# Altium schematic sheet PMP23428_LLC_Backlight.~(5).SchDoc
size 431 x 279 mm; Date: Not shown in title block; ApprovedBy: Not shown in title block; CheckedBy: Not shown in title block; Author: Not shown in title block; CompanyName: Not shown in title block; Engineer: Not shown in title block; Organization: Not shown in title block; Address1: Not shown in title block; Address2: Not shown in title block; Address3: Not shown in title block; Address4: Not shown in title block; DocumentNumber: 2; Revision: Use project parameter SCH_Rev; SheetNumber: 2; SheetTotal: 4; PageSetup: Record=PageOptions¦CenterHorizontal=True¦CenterVertical=True¦PrintScale=1.00¦XCorrection=1.00¦YCorrection=1.00¦PrintKind=0¦BorderSize=5000000¦LeftOffset=0¦BottomOffset=0¦Orientation=2¦PaperLength=1000¦PaperWidth=1000¦Scale=100¦PaperSource=15¦PrintQuality=600¦MediaType=1¦DitherType=10¦PaperKind=Letter¦PrintScaleMode=1
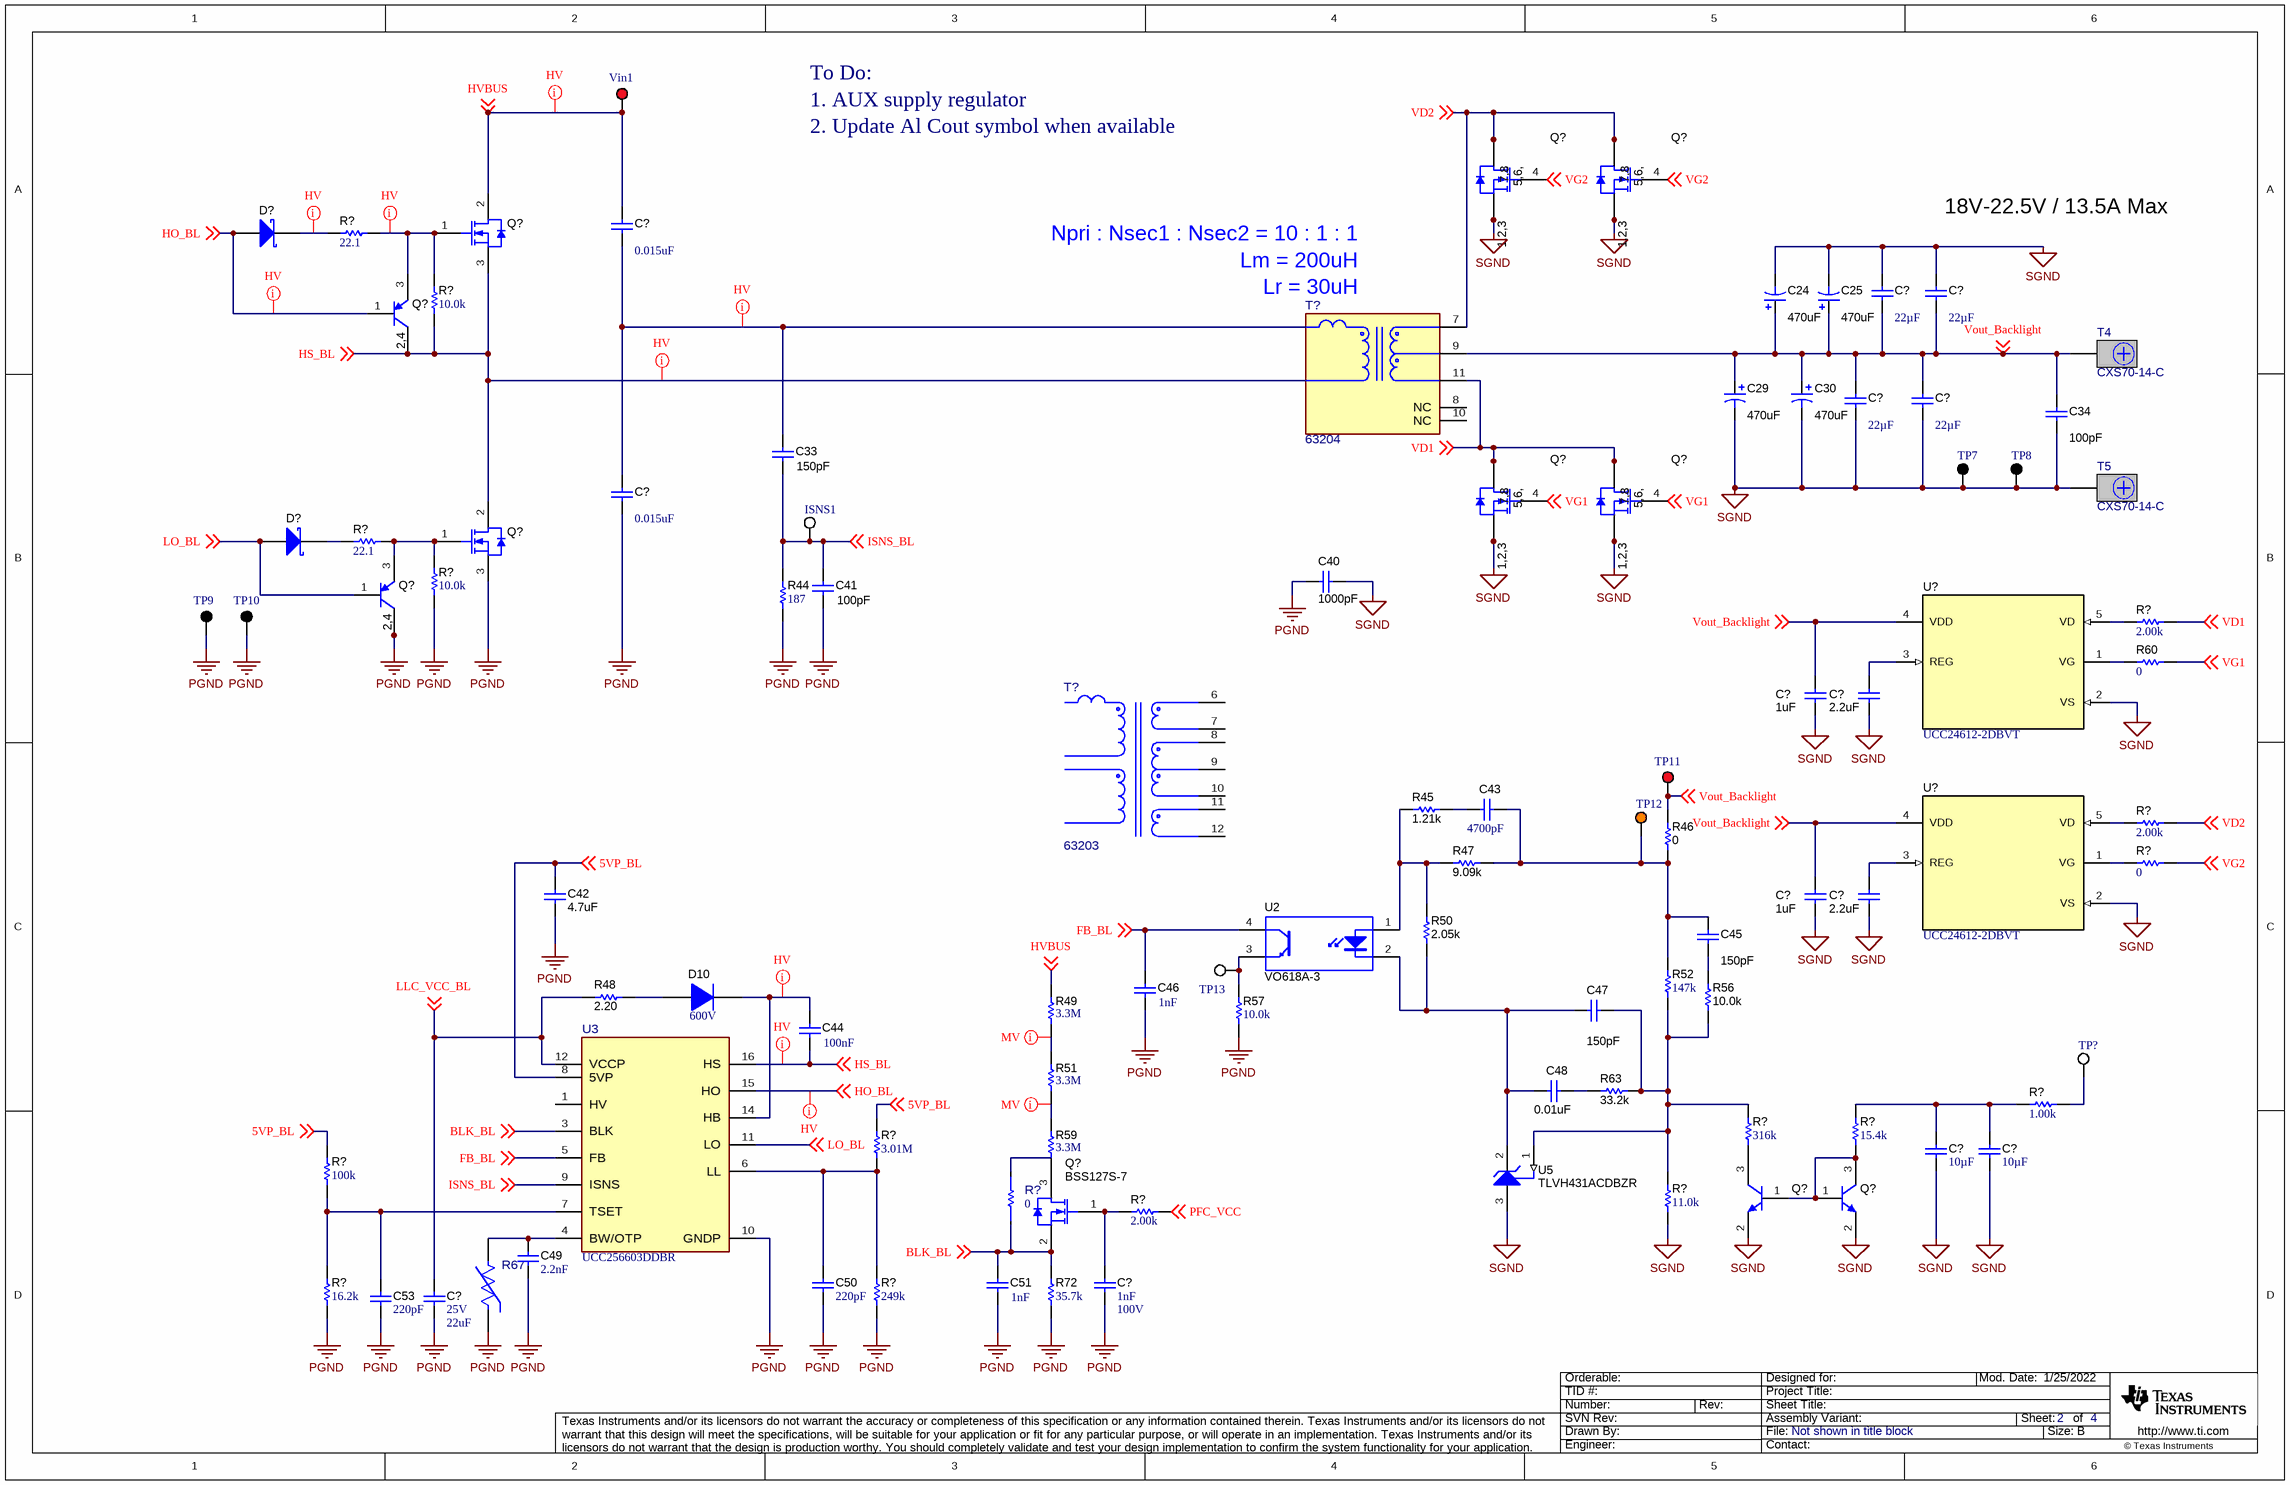
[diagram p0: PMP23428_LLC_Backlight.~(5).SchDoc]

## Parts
(Parts that share a designator on the sheet are numbered #1, #2 ... from top to bottom, then left to right.)
C24  ValueDisplayed: 470uF  [HW_1000x1600]  (hidden comment: UHW1V471MPD)
C25  ValueDisplayed: 470uF  [HW_1000x1600]  (hidden comment: UHW1V471MPD)
C29  ValueDisplayed: 470uF  [HW_1000x1600]  (hidden comment: UHW1V471MPD)
C30  ValueDisplayed: 470uF  [HW_1000x1600]  (hidden comment: UHW1V471MPD)
C33  ValueDisplayed: 150pF  [1206L]  (hidden comment: GRM31A5C2J151JW01D)
C34  ValueDisplayed: 100pF  [0603L]  (hidden comment: 06035A101FAT2A)
C40  ValueDisplayed: 1000pF  [CD45_700x600x1100]  (hidden comment: CD45-E2GA102M-NKA)
C41  ValueDisplayed: 100pF  [1206L]  (hidden comment: 12061A101JAT2A)
C42  ValueDisplayed: 4.7uF  [1206L]  (hidden comment: C3216X7R1E475K085AB)
C43  ValueDisplayed: 4700pF  [0603L]  (hidden comment: C0603C472J1GAC7867)
C44  Cap_F: 100nF  [1206_180L]  (hidden comment: GRM31C5C1E104JA01L)
C45  ValueDisplayed: 150pF  [0402L]  (hidden comment: 885012005062)
C46  Cap_F: 1nF  [1206L]  (hidden comment: 12061A102JAT2A)
C47  ValueDisplayed: 150pF  [0402L]  (hidden comment: 885012005062)
C48  ValueDisplayed: 0.01uF  [0603L]  (hidden comment: 06031C103JAT2A)
C49  Cap_F: 2.2nF  [0603]  (hidden comment: C0603X222K5RACTU)
C50  Cap_F: 220pF  [0603]  (hidden comment: C0603X221K5RACTU)
C51  Cap_F: 1nF  [0402L]  (hidden comment: 04025C102JAT2A)
C53  Cap_F: 220pF  [0603]  (hidden comment: C0603X221K5RACTU)
C?#1  ValueDisplayed: 0.015uF  [PHE426_1300x400x900]  (hidden comment: PHE426MA5150JR05)
C?#2  ValueDisplayed: 22µF  [1210]  (hidden comment: GMK325BJ226MM-P)
C?#3  ValueDisplayed: 22µF  [1210]  (hidden comment: GMK325BJ226MM-P)
C?#4  ValueDisplayed: 22µF  [1210]  (hidden comment: GMK325BJ226MM-P)
C?#5  ValueDisplayed: 22µF  [1210]  (hidden comment: GMK325BJ226MM-P)
C?#6  ValueDisplayed: 0.015uF  [PHE426_1300x400x900]  (hidden comment: PHE426MA5150JR05)
C?#7  ValueDisplayed: 1uF  [0603L]  (hidden comment: GRM188R71C105KE15D)
C?#8  ValueDisplayed: 2.2uF  [0805L]  (hidden comment: C2012X7R1V225K085AC)
C?#9  ValueDisplayed: 1uF  [0603L]  (hidden comment: GRM188R71C105KE15D)
C?#10  ValueDisplayed: 2.2uF  [0805L]  (hidden comment: C2012X7R1V225K085AC)
C?#11  ValueDisplayed: 10µF  [1206_180]  (hidden comment: C1206C106J3RACAUTO)
C?#12  ValueDisplayed: 10µF  [1206_180]  (hidden comment: C1206C106J3RACAUTO)
C?#13  Cap_F: 1nF  VDC_V: 100V  [0603]  (hidden comment: C1608X7R2A102K080AA)
C?#14  VDC_V: 25V  ValueDisplayed: 22uF  [1206_190]  (hidden comment: TMK316BBJ226ML-T)
D10  Vr_V: 600V  [SMAF]  (hidden comment: ES1JAF)
D?#1  PMEG3010EGWJ  [SOD-123]  (value not drawn)
D?#2  PMEG3010EGWJ  [SOD-123]  (value not drawn)
ISNS1  5012  [Keystone5012]  (value not drawn)
Q?#1  CSD19532Q5B  [DNK0008A]  (value not drawn)
Q?#2  CSD19532Q5B  [DNK0008A]  (value not drawn)
Q?#3  IPP60R099C7XKSA1  [TO-220AB]  (value not drawn)
Q?#4  FZT593TA  [SOT-223]  (value not drawn)
Q?#5  CSD19532Q5B  [DNK0008A]  (value not drawn)
Q?#6  CSD19532Q5B  [DNK0008A]  (value not drawn)
Q?#7  IPP60R099C7XKSA1  [TO-220AB]  (value not drawn)
Q?#8  FZT593TA  [SOT-223]  (value not drawn)
Q?#9  MMBTA05LT1G  [SOT-23]  (value not drawn)
Q?#10  MMBTA05LT1G  [SOT-23]  (value not drawn)
Q?#11  BSS127S-7  [SOT-23]
R44  ValueDisplayed: 187  [1206]  (hidden comment: RC1206FR-07187RL)
R45  ValueDisplayed: 1.21k  [0603L]  (hidden comment: RC0603FR-071K21L)
R46  ValueDisplayed: 0  [0402L]  (hidden comment: RC0402JR-070RL)
R47  ValueDisplayed: 9.09k  [0603L]  (hidden comment: RC0603FR-079K09L)
R48  ValueDisplayed: 2.20  [0603L]  (hidden comment: ERJ-3RQF2R2V)
R49  Res_ohm: 3.3M  [FP-KTR18EZPF3304_1206-MFG]  (hidden comment: KTR18EZPF3304)
R50  ValueDisplayed: 2.05k  [0603L]  (hidden comment: RC0603FR-072K05L)
R51  Res_ohm: 3.3M  [FP-KTR18EZPF3304_1206-MFG]  (hidden comment: KTR18EZPF3304)
R52  ValueDisplayed: 147k  [0603L]  (hidden comment: RC0603FR-07147KL)
R56  ValueDisplayed: 10.0k  [0603L]  (hidden comment: ERJ-3EKF1002V)
R57  ValueDisplayed: 10.0k  [0402L]  (hidden comment: ERJ-2RKF1002X)
R59  Res_ohm: 3.3M  [FP-KTR18EZPF3304_1206-MFG]  (hidden comment: KTR18EZPF3304)
R60  ValueDisplayed: 0  [0603L]  (hidden comment: RC0603JR-070RL)
R63  ValueDisplayed: 33.2k  [0603L]  (hidden comment: RC0603FR-0733K2L)
R67  B57371V2474J060  [FP-B57371V2474J060_0603-MFG]  (value not drawn)
R72  ValueDisplayed: 35.7k  [0603]  (hidden comment: RT0603BRD0735K7L)
R?#1  ValueDisplayed: 22.1  [0603]  (hidden comment: RC0603FR-0722R1L)
R?#2  ValueDisplayed: 10.0k  [0603]  (hidden comment: M55342K12B10E0T)
R?#3  ValueDisplayed: 22.1  [0603]  (hidden comment: RC0603FR-0722R1L)
R?#4  ValueDisplayed: 10.0k  [0603]  (hidden comment: M55342K12B10E0T)
R?#5  ValueDisplayed: 2.00k  [0603]  (hidden comment: RC0603FR-072KL)
R?#6  ValueDisplayed: 2.00k  [0603]  (hidden comment: RC0603FR-072KL)
R?#7  ValueDisplayed: 0  [0603L]  (hidden comment: RC0603JR-070RL)
R?#8  ValueDisplayed: 1.00k  [0603L]  (hidden comment: CRCW06031K00FKEA)
R?#9  ValueDisplayed: 316k  [0603L]  (hidden comment: CRCW0603316KFKEA)
R?#10  ValueDisplayed: 15.4k  [0603L]  (hidden comment: RC0603FR-0715K4L)
R?#11  ValueDisplayed: 3.01M  [0603]  (hidden comment: RC0603FR-073M01L)
R?#12  ValueDisplayed: 100k  [0603]  (hidden comment: RC0603FR-07100KL)
R?#13  ValueDisplayed: 11.0k  [0603]  (hidden comment: RC0603FR-0711KL)
R?#14  ValueDisplayed: 2.00k  [0603]  (hidden comment: RC0603FR-072KL)
R?#15  value 0  [FP-RMCF1206ZT0R00_1206-MFG]  (hidden comment: RMCF1206ZT0R00)
R?#16  ValueDisplayed: 16.2k  [0603]  (hidden comment: RC0603FR-0716K2L)
R?#17  ValueDisplayed: 249k  [0603]  (hidden comment: RC0603FR-07249KL)
T4  CXS70-14-C  [Panduit_CXS70-14-C]
T5  CXS70-14-C  [Panduit_CXS70-14-C]
T?#1  63204  [FP-63204_PTH_XRMS_80MM0_64MM0-MFG]
T?#2  63203  [FP-63203_W80MM0_H64MM0-MFG]
TP7  5011  [Keystone5011]  (value not drawn)
TP8  5011  [Keystone5011]  (value not drawn)
TP9  5011  [Keystone5011]  (value not drawn)
TP10  5011  [Keystone5011]  (value not drawn)
TP11  5010  [Keystone5010]  (value not drawn)
TP12  5013  [Keystone5013]  (value not drawn)
TP13  5012  [Keystone5012]  (value not drawn)
TP?  5012  [Keystone5012]  (value not drawn)
U2  VO618A-3  [DIP-4]
U3  UCC256603DDBR  [DDB0014A-MFG]
U5  TLVH431ACDBZR  [DBZ0003A_N]
U?#1  UCC24612-2DBVT  [DBV0005A_N]
U?#2  UCC24612-2DBVT  [DBV0005A_N]
Vin1  5010  [Keystone5010]  (value not drawn)

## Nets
PGND: C40.2 C41.2 C42.2 C46.2 C49.2 C50.2 C51.2 C53.2 C?#6.2 C?#13.2 C?#14.2 Q?#7.3(S) Q?#8.2(C) Q?#8.4(C) R44.1 R57.1 R67.1 R72.1 R?#4.1 R?#16.1 R?#17.1 TP9.1 TP10.1 U3.10(GNDP)
SGND: C24.2(-) C25.2(-) C29.2(-) C30.2(-) C34.2 C40.1 C?#2.1 C?#3.1 C?#4.2 C?#5.2 C?#7.2 C?#8.2 C?#9.2 C?#10.2 C?#11.2 C?#12.2 Q?#1.1(S) Q?#1.2(S) Q?#1.3(S) Q?#2.1(S) Q?#2.2(S) Q?#2.3(S) Q?#5.1(S) Q?#5.2(S) Q?#5.3(S) Q?#6.1(S) Q?#6.2(S) Q?#6.3(S) Q?#9.2(E) Q?#10.2(E) R?#13.1 T5.1 TP7.1 TP8.1 U5.3(ANODE) U?#1.2(VS) U?#2.2(VS)
5VP_BL: C42.1 R?#11.2 R?#12.2 U3.8(5VP) ; off-sheet 5VP_BL
BLK_BL: C51.1 Q?#11.2(S) R72.2 R?#15.1 U3.3(BLK) ; off-sheet BLK_BL
FB_BL: C46.1 U2.4(C) U3.5(FB) ; off-sheet FB_BL
HO_BL: D?#1.2(A) Q?#4.1(B) U3.15(HO) ; off-sheet HO_BL
HS_BL: C44.2 Q?#3.3(S) Q?#4.2(C) Q?#4.4(C) Q?#7.2(D) R?#2.1 U3.16(HS) ; off-sheet HS_BL
HVBUS: C?#1.1 Q?#3.2(D) R49.2 Vin1.1 ; off-sheet HVBUS
ISNS_BL: C33.2 C41.1 ISNS1.1 R44.2 U3.9(ISNS) ; off-sheet ISNS_BL
LLC_VCC_BL: C?#14.1 R48.1 U3.12(VCCP) ; off-sheet LLC_VCC_BL
LO_BL: D?#2.2(A) Q?#8.1(B) U3.11(LO) ; off-sheet LO_BL
PFC_VCC: R?#14.2 ; off-sheet PFC_VCC
VD1: Q?#5.5(D) Q?#5.6(D) Q?#5.7(D) Q?#5.8(D) Q?#5.9(D) Q?#6.5(D) Q?#6.6(D) Q?#6.7(D) Q?#6.8(D) Q?#6.9(D) R?#5.2 T?#1.11 ; off-sheet VD1
VD2: Q?#1.5(D) Q?#1.6(D) Q?#1.7(D) Q?#1.8(D) Q?#1.9(D) Q?#2.5(D) Q?#2.6(D) Q?#2.7(D) Q?#2.8(D) Q?#2.9(D) R?#6.2 T?#1.7 ; off-sheet VD2
VG1: Q?#5.4(G) Q?#6.4(G) R60.1 ; off-sheet VG1
VG2: Q?#1.4(G) Q?#2.4(G) R?#7.1 ; off-sheet VG2
Vout_Backlight: C24.1(+) C25.1(+) C29.1(+) C30.1(+) C34.1 C?#2.2 C?#3.2 C?#4.1 C?#5.1 C?#7.1 C?#9.1 R46.2 T4.1 T?#1.9 TP11.1 U?#1.4(VDD) U?#2.4(VDD) ; off-sheet Vout_Backlight
NetC33_1: C33.1 C?#1.2 C?#6.1
NetC43_1: C43.1 C45.1 R46.1 R47.2 R52.2 TP12.1
NetC43_2: C43.2 R45.2
NetC44_1: C44.1 D10.1(K) U3.14(HB)
NetC45_2: C45.2 R56.2
NetC47_1: C47.1 R52.1 R56.1 R63.1 R?#9.2 R?#13.2 U5.1(REF)
NetC47_2: C47.2 C48.2 R50.1 U2.2(K) U5.2(CATHODE)
NetC48_1: C48.1 R63.2
NetC49_1: C49.1 R67.2 U3.4(BW/OTP)
NetC50_1: C50.1 R?#11.1 R?#17.2 U3.6(LL)
NetC53_1: C53.1 R?#12.1 R?#16.2 U3.7(TSET)
NetC?#8_1: C?#8.1 U?#1.3(REG)
NetC?#10_1: C?#10.1 U?#2.3(REG)
NetC?#11_1: C?#11.1 C?#12.1 R?#8.1 R?#10.2
NetC?#13_1: C?#13.1 Q?#11.1(G) R?#14.1
NetD10_2: D10.2(A) R48.2
NetD?#1_1: D?#1.1(K) R?#1.1
NetD?#2_1: D?#2.1(K) R?#3.1
NetQ?#3_1: Q?#3.1(G) Q?#4.3(E) R?#1.2 R?#2.2
NetQ?#7_1: Q?#7.1(G) Q?#8.3(E) R?#3.2 R?#4.2
NetQ?#9_1: Q?#9.1(B) Q?#10.1(B) Q?#10.3(C) R?#10.1
NetQ?#9_3: Q?#9.3(C) R?#9.1
NetQ?#11_3: Q?#11.3(D) R59.1
NetR45_1: R45.1 R47.1 R50.2 U2.1(A)
NetR49_1: R49.1 R51.2
NetR51_1: R51.1 R59.2
NetR57_2: R57.2 TP13.1 U2.3(E)
NetR60_2: R60.2 U?#1.1(VG)
NetR?#5_1: R?#5.1 U?#1.5(VD)
NetR?#6_1: R?#6.1 U?#2.5(VD)
NetR?#7_2: R?#7.2 U?#2.1(VG)
NetR?#8_2: R?#8.2 TP?.1

Not connected (* = marked no-connect by the designer): R?#15 2; T?#1 8(NC) 10(NC); T?#2 6 7 8 9 10 11 12; U3 1(HV)

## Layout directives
net class HV: HO_BL, HS_BL, HVBUS, NetC33_1, NetC44_1, NetD?#1_1, NetQ?#3_1
net class MV: NetR49_1, NetR51_1

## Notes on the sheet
- To Do:
- 1. AUX supply regulator
- 2. Update Al Cout symbol when available
- Npri : Nsec1 : Nsec2 = 10 : 1 : 1
- 18V-22.5V / 13.5A Max
- Lm = 200uH
- Lr = 30uH

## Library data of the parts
C24 C25 C29 C30 = CMP-0010541-2: CAP, AL, 470 uF, 35 V, +/- 20%, 0.03 ohm, TH; Manufacturer: Nichicon; TaMin_C: -40°C; ESR_ohm: 0.03; Polarized: Y; SizeAreaWB_mm2: 144; U/M: EA; Value: 470uF; TaMax_C: 105°C; SizeZ_mm: 17.5; SizeX_mm: 10; Cap_Case: 10x16mm; Value2: 35V; SizeArea_mm2: 100; CompType: Capacitor; AEC Qualified: N; Cap_F: 470µF; IRMS_A: 2A; AEC Category: Q200
C33 = CMP-0008885-2: CAP, CERM, 150 pF, 630 V, +/- 5%, C0G/NP0, 1206; Manufacturer: MuRata; TaMin_C: -55°C; Polarized: N; SizeAreaWB_mm2: 10.92; Value1: Unknown; U/M: EA; Value: 150pF; TaMax_C: 125°C; SizeZ_mm: 1.35; SizeX_mm: 3.2; SizeY_mm: 1.6; Cap_Case: 1206; Value2: 630V; SizeArea_mm2: 5.12; CompType: Capacitor; AEC Category: Q200
C34 = CMP-0006762-4: CAP, CERM, 100 pF, 50 V, +/- 1%, C0G/NP0, 0603; Manufacturer: AVX; TaMin_C: -55°C; Polarized: N; SizeAreaWB_mm2: 4.68; Value1: Unknown; U/M: EA; TaMax_C: 125°C; SizeZ_mm: 1; SizeX_mm: 1.6; SizeY_mm: 0.8; Cap_Case: 0603; Value2: 50V; SizeArea_mm2: 1.28; CompType: Capacitor; Value: 100pF; AEC Category: Q200
C40 = CMP-0009595-2: CAP, CERM, 1000 pF,  V, +/- 20%, E, D7xT6mm; Manufacturer: TDK; TaMin_C: -25°C; Polarized: N; SizeAreaWB_mm2: 101.2; Value1: Unknown; U/M: EA; Value: 1000pF; TaMax_C: 125°C; SizeZ_mm: 11; SizeX_mm: 10.65; SizeY_mm: 6; Cap_Case: 7x6x11mm; SizeArea_mm2: 63.9; Cap_F: 1nF; AEC Category: Q200
C41 = CMP-0008462-2: CAP, CERM, 100 pF, 100 V, +/- 5%, C0G/NP0, 1206; Manufacturer: AVX; TaMin_C: -55°C; ESR_ohm: 7.01d; Polarized: N; SizeAreaWB_mm2: 10.92; Value1: 0.701 ohm; U/M: EA; Value: 100pF; TaMax_C: 125°C; SizeZ_mm: 1.35; SizeX_mm: 3.2; SizeY_mm: 1.6; Cap_Case: 1206; Value2: 100V; SizeArea_mm2: 5.12; CompType: Capacitor; AEC Category: Q200
C42 = CMP-0008693-2: CAP, CERM, 4.7 uF, 25 V, +/- 10%, X7R, 1206; Manufacturer: TDK; TaMin_C: -55°C; Polarized: N; SizeAreaWB_mm2: 10.92; Value1: Unknown; U/M: EA; Value: 4.7uF; TaMax_C: 125°C; SizeZ_mm: 1.35; SizeX_mm: 3.2; SizeY_mm: 1.6; Cap_Case: 1206; Value2: 25V; SizeArea_mm2: 5.12; CompType: Capacitor; Cap_F: 4.7µF; AEC Category: Q200
C43 = CMP-0006941-4: CAP, CERM, 4700 pF, 100 V, +/- 5%, C0G/NP0, 0603; Manufacturer: Kemet; TaMin_C: -55°C; Polarized: N; SizeAreaWB_mm2: 4.68; Value1: Unknown; U/M: EA; Value: 4700pF; TaMax_C: 125°C; SizeZ_mm: 1; SizeX_mm: 1.6; SizeY_mm: 0.8; Cap_Case: 0603; Value2: 100V; SizeArea_mm2: 1.28; Cap_F: 4.7nF; AEC Category: Q200
C44 = CMP-0064950-2: CAP, CERM, 0.1 uF, 25 V,+/- 5%, C0G/NP0, 1206; Manufacturer: MuRata; TaMin_C: -55°C; Polarized: N; SizeAreaWB_mm2: 10.92; Value1: Unknown; U/M: EA; Value: 0.1uF; TaMax_C: 125°C; SizeZ_mm: 1.8; SizeX_mm: 3.2; SizeY_mm: 1.6; Cap_Case: 1206; Value2: 25V; SizeArea_mm2: 5.12; AEC Category: Q200
C45 C47 = CMP-0064913-2: CAP, CERM, 150 pF, 50 V,+/- 5%, C0G/NP0, 0402; Manufacturer: Wurth Elektronik; TaMin_C: -55°C; Polarized: N; SizeAreaWB_mm2: 3; Value1: Unknown; U/M: EA; Value: 150pF; TaMax_C: 125°C; SizeZ_mm: 0.6; SizeX_mm: 1; SizeY_mm: 0.5; Cap_Case: 0402; Value2: 50V; CompType: Capacitor; AEC Category: Q200
C46 = CMP-0008465-2: CAP, CERM, 1000 pF, 100 V, +/- 5%, C0G/NP0, 1206; Manufacturer: AVX; TaMin_C: -55°C; ESR_ohm: 2.38d; Polarized: N; SizeAreaWB_mm2: 10.92; Value1: 0.238 ohm; U/M: EA; Value: 1000pF; TaMax_C: 125°C; SizeZ_mm: 1.35; SizeX_mm: 3.2; SizeY_mm: 1.6; Cap_Case: 1206; Value2: 100V; SizeArea_mm2: 5.12; AEC Category: Q200
C48 = CMP-0006726-4: CAP, CERM, 0.01 uF, 100 V, +/- 5%, X7R, 0603; Manufacturer: AVX; TaMin_C: -55°C; ESR_ohm: 0.098; Polarized: N; SizeAreaWB_mm2: 4.68; Value1: 0.098 ohm; U/M: EA; Value: 0.01uF; TaMax_C: 125°C; SizeZ_mm: 1; SizeX_mm: 1.6; SizeY_mm: 0.8; Cap_Case: 0603; Value2: 100V; SizeArea_mm2: 1.28; Cap_F: 10nF; AEC Category: Q200
C49 = CMP-0006983-4: CAP, CERM, 2200 pF, 50 V, +/- 10%, X7R, 0603; Manufacturer: Kemet; TaMin_C: -55°C; Polarized: N; SizeAreaWB_mm2: 4.68; Value1: Unknown; U/M: EA; Value: 2200pF; TaMax_C: 125°C; SizeZ_mm: 1; SizeX_mm: 1.6; SizeY_mm: 0.8; Value2: 50V; SizeArea_mm2: 1.28; AEC Category: Q200
C50 C53 = CMP-0006982-4: CAP, CERM, 220 pF, 50 V, +/- 10%, X7R, 0603; Manufacturer: Kemet; TaMin_C: -55°C; Polarized: N; SizeAreaWB_mm2: 4.68; Value1: Unknown; U/M: EA; Value: 220pF; TaMax_C: 125°C; SizeZ_mm: 1; SizeX_mm: 1.6; SizeY_mm: 0.8; Value2: 50V; SizeArea_mm2: 1.28; AEC Category: Q200
C51 = CMP-0861060-1: CAP, CERM, 1000 pF, 50 V,+/- 5%, X7R, 0402; Manufacturer: AVX; Value2: 50V; SizeY_mm: 0.5; AEC Category: Q200; Polarized: N; Green_Lifecycle: Active; SizeAreaWB_mm2: 3; ValueDisplayed: 1000pF; Cap_Case: 0402; Value: 1000pF; TaMin_C: -55°C; U/M: EA; Green_REACh: Passed; SizeZ_mm: 0.6; SizeX_mm: 1; TaMax_C: 125°C
C?#1 C?#6 = CMP-0012541-3: CAP, Film, 0.015 uF, 630 V, +/- 20%, TH; Manufacturer: Kemet; TaMin_C: -55°C; Polarized: N; SizeAreaWB_mm2: 90; Value1: Unknown; TaMax_C: 105°C; SizeZ_mm: 9; SizeX_mm: 13; SizeY_mm: 4; Cap_Case: 13x4x9mm; Value2: 630V; SizeArea_mm2: 52; Cap_F: 15nF; AEC Category: Q200
C?#2-C?#5 = CMP-0085817-1: CAP, CERM, 22 µF, 35 V,+/- 20%, X5R, 1210; Manufacturer: Taiyo Yuden; Value: 22uF; VDC_V: 35V; SizeZ_mm: 1.35; TaMax_C: 85°C; U/M: EA; SizeAreaWB_mm2: 14.7; SizeX_mm: 3.2; SizeArea_mm2: 8; TaMin_C: -55°C; AEC Qualified: N; SizeY_mm: 2.5; AEC Category: Q200
C?#7 C?#9 = CMP-0007380-4: CAP, CERM, 1 uF, 16 V, +/- 10%, X7R, 0603; Manufacturer: MuRata; TaMin_C: -55°C; Polarized: N; SizeAreaWB_mm2: 4.68; Value1: Unknown; U/M: EA; Value: 1uF; TaMax_C: 125°C; SizeZ_mm: 1; SizeX_mm: 1.6; SizeY_mm: 0.8; Cap_Case: 0603; Value2: 16V; SizeArea_mm2: 1.28; CompType: Capacitor; Cap_F: 1µF; AEC Category: Q200
C?#8 C?#10 = CMP-0007883-2: CAP, CERM, 2.2 uF, 35 V, +/- 10%, X7R, 0805; Manufacturer: TDK; TaMin_C: -55°C; Polarized: N; SizeAreaWB_mm2: 6.75; Value1: Unknown; U/M: EA; Value: 2.2uF; TaMax_C: 125°C; SizeZ_mm: 1.45; SizeX_mm: 2; SizeY_mm: 1.25; Cap_Case: 0805; Value2: 35V; SizeArea_mm2: 2.5; CompType: Capacitor; Cap_F: 2.2µF; AEC Category: Q200
C?#11 C?#12 = CMP-0081062-1: CAP, CERM, 10 µF, 25 V,+/- 5%, X7R, AEC-Q200 Grade 1, 1206; Manufacturer: Kemet; TaMin_C: -55°C; Polarized: N; SizeAreaWB_mm2: 10.92; U/M: EA; Value: 10uF; TaMax_C: 125°C; SizeZ_mm: 1.8; SizeX_mm: 3.2; SizeY_mm: 1.6; Value2: 25V; SizeArea_mm2: 5.12; AEC Qualified: Y; AEC Grade: 1; AEC Category: Q200
C?#13 = CMP-0007053-4: CAP, CERM, 1000 pF, 100 V, +/- 10%, X7R, 0603; Manufacturer: TDK; TaMin_C: -55°C; Polarized: N; SizeAreaWB_mm2: 4.68; Value1: Unknown; U/M: EA; Value: 1000pF; TaMax_C: 125°C; SizeZ_mm: 1; SizeX_mm: 1.6; SizeY_mm: 0.8; SizeArea_mm2: 1.28; AEC Category: Q200
C?#14 = CMP-0009024-2: CAP, CERM, 22 uF, 25 V, +/- 20%, X5R, 1206_190; Manufacturer: Taiyo Yuden; TaMin_C: -55°C; Polarized: N; SizeAreaWB_mm2: 10.92; Value1: Unknown; U/M: EA; Value: 22uF; TaMax_C: 85°C; SizeZ_mm: 1.9; SizeX_mm: 3.2; SizeY_mm: 1.6; Cap_Case: 1206; SizeArea_mm2: 5.12; Cap_F: 22µF; AEC Category: Q200
D10 = CMP-0029162-2: Diode, Ultrafast, 600 V, 1 A, AEC-Q101, SMAF; Manufacturer: Fairchild Semiconductor; Io_A: 1A; Green_Lifecycle: Not Set; SizeAreaWB_mm2: 19.95; Green_REACh: Incomplete; TJmax_C: 150°C; Value: 600V; SizeZ_mm: 1; SizeX_mm: 4.7; SizeY_mm: 2.5; Vf_V: 1.7V; SizeArea_mm2: 11.75; AEC Qualified: Y; AEC Category: Q101
D?#1 D?#2 = CMP-0079240-2: Diode, Schottky, 30 V, 1 A, AEC-Q101, SOD-123; Manufacturer: Nexperia; SizeZ_mm: 1.35; Value: 30V; Value1: 1A; AEC Category: Q101; Vf_V: 560mV; SizeX_mm: 3.85; SizeAreaWB_mm2: 13.095; Value2: 0.56V; SizeY_mm: 1.7; AEC Qualified: Y; TJmax_C: 150°C; SizeArea_mm2: 6.545
ISNS1 TP13 = CMP-0055149-2: Test Point, Multipurpose, White, TH; Manufacturer: Keystone Electronics; CNHeader: FALSE; Green_Lifecycle: Active; Green_REACh: Passed; ContactFinish: Silver; CT: TRUE
Q?#1 Q?#2 Q?#5 Q?#6 = CMP-0000958-3: MOSFET, N-CH, 100 V, 17 A, DNK0008A (VSON-CLIP-8); Alternate Manufacturer: None; Manufacturer: Texas Instruments; SizeZ_mm: 1; ChType: N; Value2: 48 nC; VdsMax_V: 100V; SizeX_mm: 6; SizeY_mm: 5; Vgs_V: 20V; QgTyp_nC: 48; Value: 100V; SizeArea_mm2: 30; AEC Category: Q101; IdsMax_A: 17A; SizeAreaWB_mm2: 56; U/M: EA
Q?#3 Q?#7 = CMP-0001171-3: MOSFET, N-CH, 600 V, 22 A, TO-220AB; Alternate Manufacturer: None; Manufacturer: Infineon Technologies; SizeZ_mm: 19.4; ChType: N; Value2: 42 nC; VdsMax_V: 600V; SizeX_mm: 10.2; SizeY_mm: 4.5; Vgs_V: 30V; QgTyp_nC: 42; Value: 600V; SizeArea_mm2: 45.9; AEC Category: Q101; IdsMax_A: 22A; SizeAreaWB_mm2: 79.3; U/M: EA
Q?#4 Q?#8 = CMP-0000361-2: Transistor, PNP, 100 V, 1 A, AEC-Q101, SOT-223; Manufacturer: Diodes Inc.; TaMax_C: 150°C; Value2: 300; Value1: 1 A; Vcesat1_V: 3dV; SizeX_mm: 6.5; SizeY_mm: 7; TaMin_C: -55°C; IcRated_A: 1A; CompType: BJT; SizeZ_mm: 1.6; AEC Qualified: Y; Value: 100 V; SizeArea_mm2: 45.5; NPN: 0; Vceo_V: 100V; PNP: 1; AEC Category: Q101; SizeAreaWB_mm2: 76.5; U/M: EA
Q?#9 Q?#10 = CMP-0000488-2: Transistor, NPN, 60 V, 0.5 A, AEC-Q101, SOT-23; Manufacturer: ON Semiconductor; TaMax_C: 150°C; Value1: 0.5 A; Vcesat1_V: 2.5dV; SizeX_mm: 2.5; SizeY_mm: 3; TaMin_C: -55°C; IcRated_A: 5dA; CompType: BJT; SizeZ_mm: 1.1; AEC Qualified: Y; Value: 60 V; SizeArea_mm2: 7.5; NPN: 1; Vceo_V: 60V; PNP: 0; AEC Category: Q101; SizeAreaWB_mm2: 14; U/M: EA
Q?#11 = CMP-0001149-3: MOSFET, N-CH, 600 V, 0.05 A, SOT-23; Alternate Manufacturer: None; Manufacturer: Diodes Inc.; SizeZ_mm: 1.1; ChType: N; Value2: 1.08 nC; VdsMax_V: 600V; SizeX_mm: 2.5; SizeY_mm: 3; Vgs_V: 20V; QgTyp_nC: 1.08; Value: 600V; SizeArea_mm2: 7.5; AEC Category: Q101; IdsMax_A: 50mA; SizeAreaWB_mm2: 14; U/M: EA
R44 = CMP-0017949-2: RES, 187, 1%, 0.25 W, 1206; Manufacturer: Yageo America; Power_W: 250mW; TempCo: 100 ppm/C; Value_Code: 187R; U/M: EA; Value: 187; EIA_Code: E96; SizeX_mm: 3.2; SizeY_mm: 1.6; SizeZ_mm: 1.35; Value2: 0.25W; SizeArea_mm2: 5.12; VDC_V: 200V; AEC Category: Q200
R45 = CMP-0022871-5: RES, 1.21 k, 1%, 0.1 W, 0603; Manufacturer: Yageo; Power_W: 100mW; TempCo: 100 ppm/C; Value_Code: 1k21; Value: 1.21k; EIA_Code: E96; SizeX_mm: 1.6; SizeY_mm: 0.8; SizeZ_mm: 1; Value2: 0.1W; SizeArea_mm2: 1.28; AEC Qualified: N; VDC_V: 75V; AEC Category: Q200; SizeAreaWB_mm2: 4.68
R46 = CMP-0027004-2: RES, 0, 5%, 0.063 W, 0402; Manufacturer: Yageo America; Power_W: 63mW; TempCo: 200 ppm/C; Value_Code: 0000; U/M: EA; Value: 0; EIA_Code: E24; SizeX_mm: 1; SizeY_mm: 0.5; SizeZ_mm: 0.6; Value2: 0.063W; CompType: Resistor; VDC_V: 50V; AEC Category: Q200
R47 = CMP-0023332-5: RES, 9.09 k, 1%, 0.1 W, 0603; Manufacturer: Yageo; Power_W: 100mW; TempCo: 100 ppm/C; Value_Code: 9k09; Value: 9.09k; EIA_Code: E96; SizeX_mm: 1.6; SizeY_mm: 0.8; SizeZ_mm: 1; Value2: 0.1W; SizeArea_mm2: 1.28; AEC Qualified: N; VDC_V: 75V; AEC Category: Q200; SizeAreaWB_mm2: 4.68
R48 = CMP-0022711-2: RES, 2.20, 1%, 0.1 W, 0603; Manufacturer: Panasonic; Power_W: 100mW; TempCo: 200 ppm/C; Value_Code: 2R20; U/M: EA; Value: 2.20; Res_ohm: 2.2; SizeX_mm: 1.6; SizeY_mm: 0.8; SizeZ_mm: 1; Value2: 0.1W; SizeArea_mm2: 1.28; CompType: Resistor; AEC Category: Q200
R49 R51 R59 = CMP-0087456-2: 3.3 MOhms ±1% 0.25W, 1/4W Chip Resistor 1206 (3216 Metric) Automotive AEC-Q200, High Voltage Thick Film; Manufacturer: Rohm Semiconductor; AEC Qualified: Yes; Power_W: 250mW; SizeZ_mm: 0.65mm; AEC Grade: Grade 0; TempCo: 100ppm/°C; VDC_V: 500V
R50 = CMP-0022981-5: RES, 2.05 k, 1%, 0.1 W, 0603; Manufacturer: Yageo; Power_W: 100mW; TempCo: 100 ppm/C; Value_Code: 2k05; Value: 2.05k; EIA_Code: E96; SizeX_mm: 1.6; SizeY_mm: 0.8; SizeZ_mm: 1; Value2: 0.1W; SizeArea_mm2: 1.28; AEC Qualified: N; VDC_V: 75V; AEC Category: Q200; SizeAreaWB_mm2: 4.68
R52 = CMP-0022800-4: RES, 147 k, 1%, 0.1 W, 0603; Manufacturer: Yageo; Power_W: 100mW; TempCo: 100 ppm/C; Value: 147k; EIA_Code: E96; SizeX_mm: 1.6; SizeY_mm: 0.8; SizeZ_mm: 1; Value2: 0.1W; SizeArea_mm2: 1.28; AEC Qualified: N; VDC_V: 75V; AEC Category: Q200; SizeAreaWB_mm2: 4.68
R56 = CMP-0022684-3: RES, 10.0 k, 1%, 0.1 W, 0603; Manufacturer: Panasonic; Power_W: 100mW; TempCo: 100 ppm/C; Value_Code: 10k0; U/M: EA; Value: 10.0k; EIA_Code: E96; Res_ohm: 10k; SizeX_mm: 1.6; SizeY_mm: 0.8; SizeZ_mm: 1; Value2: 0.1W; SizeArea_mm2: 1.28; CompType: Resistor; VDC_V: 75V; AEC Category: Q200
R57 = CMP-0026658-1: RES, 10.0 k, 1%, 0.1 W, 0402; Manufacturer: Panasonic; Power_W: 100mW; TempCo: 100 ppm/C; Value_Code: 10k0; U/M: EA; Value: 10.0k; EIA_Code: E96; Res_ohm: 10k; SizeX_mm: 1; SizeY_mm: 0.5; SizeZ_mm: 0.6; Value2: 0.1W; VDC_V: 50V; AEC Category: Q200
R60 R?#7 = CMP-0025885-5: RES, 0, 5%, 0.1 W, 0603; Manufacturer: Yageo; Power_W: 100mW; TempCo: 200 ppm/C; Value_Code: 0000; Value: 0; EIA_Code: E24; SizeX_mm: 1.6; SizeZ_mm: 1; Value2: 0.1W; SizeArea_mm2: 1.28; AEC Qualified: N; VDC_V: 75V; AEC Category: Q200; SizeY_mm: 0.8; SizeAreaWB_mm2: 4.68
R63 = CMP-0023036-5: RES, 33.2 k, 1%, 0.1 W, 0603; Manufacturer: Yageo; Power_W: 100mW; TempCo: 100 ppm/C; Value_Code: 33k2; Value: 33.2k; EIA_Code: E96; SizeX_mm: 1.6; SizeY_mm: 0.8; SizeZ_mm: 1; Value2: 0.1W; SizeArea_mm2: 1.28; AEC Qualified: N; VDC_V: 75V; AEC Category: Q200; SizeAreaWB_mm2: 4.68
R67 = CMP-0096703-1: NTC Thermistor 470k 0603 (1608 Metric); Manufacturer: TDK; AEC Qualified: No; Res_ohm: 470kΩ; Power_W: 180mW; B 25 50: 4386K; B 25 100: 4480K; SizeZ_mm: 0.9mm; B 25 85: 4455K; B Tolerance: 3%; Tolerance_%: 5%
R72 = CMP-0024147-3: RES, 35.7 k, 0.1%, 0.1 W, 0603; Manufacturer: Yageo America; Power_W: 100mW; TempCo: 25 ppm/C; Value_Code: 35k7; U/M: EA; Value: 35.7k; EIA_Code: E192; SizeX_mm: 1.6; SizeY_mm: 0.8; SizeZ_mm: 1; Value2: 0.1W; SizeArea_mm2: 1.28; VDC_V: 75V; AEC Category: Q200
R?#1 R?#3 = CMP-0022926-4: RES, 22.1, 1%, 0.1 W, 0603; Manufacturer: Yageo; Power_W: 100mW; TempCo: 100 ppm/C; Value_Code: 22R1; Value: 22.1; EIA_Code: E96; SizeX_mm: 1.6; SizeY_mm: 0.8; SizeZ_mm: 1; Value2: 0.1W; SizeArea_mm2: 1.28; AEC Qualified: N; VDC_V: 75V; AEC Category: Q200; SizeAreaWB_mm2: 4.68
R?#2 R?#4 = CMP-0080488-1: RES, 10.0 k, 1%, 0.1 W, 0603; Manufacturer: TT Electronics/IRC; Power_W: 100mW; TempCo: 100 ppm/C; SizeAreaWB_mm2: 4.68; Value_Code: 10k0; Value: 10.0k; EIA_Code: E96; Res_ohm: 10k; SizeX_mm: 1.6; SizeY_mm: 0.8; SizeZ_mm: 1; Value2: 0.1W; SizeArea_mm2: 1.28; AEC Qualified: N; AEC Category: Q200
R?#5 R?#6 R?#14 = CMP-0023000-5: RES, 2.00 k, 1%, 0.1 W, 0603; Manufacturer: Yageo; Power_W: 100mW; TempCo: 100 ppm/C; Value_Code: 2k00; Value: 2.00k; EIA_Code: E96; Res_ohm: 2k; SizeX_mm: 1.6; SizeY_mm: 0.8; SizeZ_mm: 1; Value2: 0.1W; SizeArea_mm2: 1.28; AEC Qualified: N; VDC_V: 75V; AEC Category: Q200; SizeAreaWB_mm2: 4.68
R?#8 = CMP-0022109-5: RES, 1.00 k, 1%, 0.1 W, AEC-Q200 Grade 0, 0603; Manufacturer: Vishay-Dale; Power_W: 100mW; TempCo: 100 ppm/C; Value_Code: 1k00; Value: 1.00k; EIA_Code: E96; Res_ohm: 1k; SizeX_mm: 1.6; SizeY_mm: 0.8; SizeZ_mm: 1; Value2: 0.1W; SizeArea_mm2: 1.28; AEC Qualified: Y; VDC_V: 75V; AEC Category: Q200; AEC Grade: 0
R?#9 = CMP-0022328-4: RES, 316 k, 1%, 0.1 W, AEC-Q200 Grade 0, 0603; Manufacturer: Vishay-Dale; Power_W: 100mW; TempCo: 100 ppm/C; Value: 316k; EIA_Code: E96; SizeX_mm: 1.6; SizeY_mm: 0.8; SizeZ_mm: 1; Value2: 0.1W; SizeArea_mm2: 1.28; AEC Qualified: Y; VDC_V: 75V; AEC Category: Q200; AEC Grade: 0
R?#10 = CMP-0022814-5: RES, 15.4 k, 1%, 0.1 W, 0603; Manufacturer: Yageo; Power_W: 100mW; TempCo: 100 ppm/C; Value_Code: 15k4; Value: 15.4k; EIA_Code: E96; SizeX_mm: 1.6; SizeY_mm: 0.8; SizeZ_mm: 1; Value2: 0.1W; SizeArea_mm2: 1.28; AEC Qualified: N; VDC_V: 75V; AEC Category: Q200; SizeAreaWB_mm2: 4.68
R?#11 = CMP-0023092-4: RES, 3.01 M, 1%, 0.1 W, 0603; Manufacturer: Yageo; Power_W: 100mW; TempCo: 100 ppm/C; Value_Code: 3M01; Value: 3.01Meg; EIA_Code: E96; SizeX_mm: 1.6; SizeY_mm: 0.8; SizeZ_mm: 1; Value2: 0.1W; SizeArea_mm2: 1.28; AEC Qualified: N; VDC_V: 75V; AEC Category: Q200; SizeAreaWB_mm2: 4.68
R?#12 = CMP-0022735-5: RES, 100 k, 1%, 0.1 W, 0603; Manufacturer: Yageo; Power_W: 100mW; TempCo: 100 ppm/C; Value: 100k; EIA_Code: E96; SizeX_mm: 1.6; SizeY_mm: 0.8; SizeZ_mm: 1; Value2: 0.1W; SizeArea_mm2: 1.28; AEC Qualified: N; VDC_V: 75V; AEC Category: Q200; SizeAreaWB_mm2: 4.68
R?#13 = CMP-0022763-5: RES, 11.0 k, 1%, 0.1 W, 0603; Manufacturer: Yageo; Power_W: 100mW; TempCo: 100 ppm/C; Value_Code: 11k0; Value: 11.0k; EIA_Code: E96; Res_ohm: 11k; SizeX_mm: 1.6; SizeY_mm: 0.8; SizeZ_mm: 1; Value2: 0.1W; SizeArea_mm2: 1.28; AEC Qualified: N; VDC_V: 75V; AEC Category: Q200; SizeAreaWB_mm2: 4.68
R?#15 = CMP-0093609-1: 0Ω ±0 0.25W 1206 Thick Film Chip Resistor AEC-Q200 compliant; Manufacturer: Stackpole Electronics; AEC Qualified: Yes; VDC_V: 200V; AEC Grade: Grade 0; Power_W: 250mW; SizeZ_mm: 0.7mm
R?#16 = CMP-0022828-5: RES, 16.2 k, 1%, 0.1 W, 0603; Manufacturer: Yageo; Power_W: 100mW; TempCo: 100 ppm/C; Value_Code: 16k2; Value: 16.2k; EIA_Code: E96; SizeX_mm: 1.6; SizeY_mm: 0.8; SizeZ_mm: 1; Value2: 0.1W; SizeArea_mm2: 1.28; AEC Qualified: N; VDC_V: 75V; AEC Category: Q200; SizeAreaWB_mm2: 4.68
R?#17 = CMP-0022941-4: RES, 249 k, 1%, 0.1 W, 0603; Manufacturer: Yageo; Power_W: 100mW; TempCo: 100 ppm/C; Value: 249k; EIA_Code: E96; SizeX_mm: 1.6; SizeY_mm: 0.8; SizeZ_mm: 1; Value2: 0.1W; SizeArea_mm2: 1.28; AEC Qualified: N; VDC_V: 75V; AEC Category: Q200; SizeAreaWB_mm2: 4.68
T4 T5 = CMP-0075010-2: Terminal 70A Lug; Manufacturer: Panduit; CNHeader: False; Green_Lifecycle: Not Set; Green_REACh: Incomplete; CompType: Screw Terminal
T?#1 = CMP-0120310-1: Backlight LLC Transformer; Manufacturer: Payton Planar; Ind_H: 200µH; Ns1toNp: 10:1+1; SizeZ_mm: 10mm; AEC Qualified: No; Frequency_Fixed: 80-250kHz; TaMax_C: +30°C; TaMin_C: -40°C; Voltage_Isolation_Vrms: 2500VDC
T?#2 = CMP-0120309-1: Transformer; Manufacturer: Payton Planar; Ind_H: 250µH; Ns1toNp: 15:2; SizeZ_mm: 10mm; AEC Qualified: No; Frequency_Fixed: 70-160kHz; TaMax_C: +30°C; TaMin_C: -40°C; Voltage_Isolation_Vrms: 2500VDC
TP7 TP8 = CMP-0055148-2: Test Point, Multipurpose, Black, TH; Manufacturer: Keystone Electronics; CNHeader: FALSE; ContactFinish: Silver; Green_REACh: Passed; Green_Lifecycle: Active; CT: TRUE
TP9 TP10 = CMP-0055148-2: Test Point, Multipurpose, Black, TH; Manufacturer: Keystone Electronics; CNHeader: FALSE; Green_Lifecycle: Active; Green_REACh: Passed; ContactFinish: Silver; CT: TRUE
TP11 Vin1 = CMP-0055147-2: Test Point, Multipurpose, Red, TH; Manufacturer: Keystone Electronics; CNHeader: FALSE; Green_Lifecycle: Active; Green_REACh: Passed; ContactFinish: Silver; CT: TRUE
TP12 = CMP-0055150-2: Test Point, Multipurpose, Orange, TH; Manufacturer: Keystone Electronics; CNHeader: FALSE; Green_Lifecycle: Active; Green_REACh: Passed; ContactFinish: Silver; CT: TRUE
TP? = CMP-0055149-2: Test Point, Multipurpose, White, TH; Manufacturer: Keystone Electronics; ContactFinish: Silver; CT: TRUE; CNHeader: FALSE; Green_Lifecycle: Active; Green_REACh: Passed
U2 = CMP-0083653-1: Optocoupler, 5.3 kV, 100-200% CTR, SMT; Manufacturer: Vishay-Semiconductor; CTR (Max): 200%; SizeAreaWB_mm2: 71.064; CTR (Min): 100%; SizeZ_mm: 5; SizeX_mm: 8.8; SizeY_mm: 4.58; SizeArea_mm2: 40.304; Voltage_Isolation_Vrms: 5.3kV
U3 = CMP-0095299-1: 750kHz Wide VIN/VOUT Range LLC Controller Optimized for Light Load Efficiency; Manufacturer: Texas Instruments; Number Of Outputs: 2; TaMax_C: +125°C; Output Type: Other; TJmax_C: +150°C; AEC Qualified: No; Standoff Height: 0.1mm; TaMin_C: -40°C; SizeZ_mm: 1.75mm; Switching Frequency: 30-750kHz; Max Supply Voltage: 18.5V
U5 = CMP-0033066-1: Low-Voltage Adjustable Precision Shunt Regulator, 129 ppm / degC, 80 mA, 0 to 70 degC, 3-pin SOT-23 (DBZ), Green (RoHS & no Sb/Br); Manufacturer: Texas Instruments; Min Iz for Regulation(uA): 80; VO Adj(Max)(V): 18; VO Adj(Min)(V): 1.24; Rating: Catalog; SubFamily: Shunt Voltage Reference; Temp Coeff(Max)(ppm/ degree C): 129
U?#1 U?#2 = CMP-0013047-3: High-Frequency Multi-Mode Synchronous Rectifier Controller, DBV0005A (SOT-23-5); Manufacturer: Texas Instruments; Alternate PartNumber: UCC24612-2DBVR; SizeX_mm: 2.8; SizeY_mm: 2.9; CompType: IC; SizeZ_mm: 1.45; SizeArea_mm2: 8.12; SizeAreaWB_mm2: 14.82; AEC Category: Q200; AEC Qualified: N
